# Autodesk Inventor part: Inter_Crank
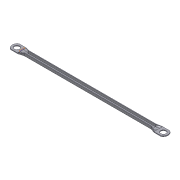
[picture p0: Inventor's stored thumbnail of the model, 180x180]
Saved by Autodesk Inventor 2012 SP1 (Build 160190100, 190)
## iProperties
Created: 2006-03
Part Number: Inter_Crank
Document SubType Name: Modeling
Material: Stainless Steel, 440C
Density: 7.75 g/cm^3
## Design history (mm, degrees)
sketch "Sketch1"
  geometry: L1 (0, 0)-(0, 1.6); L2 (0, 1.6)-(4.6, 1.6); L3 (4.6, 1.6)-(4.6, 8); L4 (4.6, 8)-(6.2, 8); L5 (6.2, 8)-(6.2, 1.5); L6 (4.7, 0)-(0, 0); L7 (0, 10.493)-(0, -1.142) reference; L8 (-4.6, 1.6)-(-4.6, 8); L9 (-4.6, 8)-(-6.2, 8); L10 (-6.2, 8)-(-6.2, 1.5); L11 (0, 1.6)-(-4.6, 1.6); L12 (-4.7, 0)-(0, 0); A1 r 1.5 centre (4.7, 1.5) between (4.7, 0) and (6.2, 1.5); A2 r 1.5 centre (-4.7, 1.5) between (-6.2, 1.5) and (-4.7, 0)
  constraints: 22 end point, 6 symmetric about line, 4 parallel, 4 point on circle, 2 centre point, 2 perpendicular, 2 tangent, 1 vertical, 1 other
  dimensions: "d1" = 4.6 distance between parallel lines of L3 L1; "d2" = 8 distance between parallel lines of L6 L4; "d3" = 1.6 distance between parallel lines of L5 L3; "d4" = 1.5 radius of A1
extrude "Extrusion1" new body sketch "Sketch1" distance "d5" = 175; taper "d6" = 0 deg
workplane "Work Plane1"
sketch "Sketch2"
  geometry: L1 (-0.8, 0)-(10.4, 0) reference; L2 (3, 12)-(5, 12); L3 (5, 12)-(5, -12); L4 (5, -12)-(3, -12); L5 (3, -12)-(3, 12); L6 (3, 12)-(5, -12); L7 (1.5, 6.2)-(8, 6.2) reference; L8 (8, -6.2)-(1.5, -6.2) reference; L9 (0, -4.7)-(0, 4.7) reference; 2 further points
  constraints: 10 end point, 2 parallel, 1 horizontal, 1 midpoint, 1 perpendicular, 1 point on line
  dimensions: "d8" = 4 distance from line of point (4, 0) L9; "d9" = 2 distance of L2.start L2.end; "d10" = 24 distance of L2.end L3.end
loft "Loft1" sketch "Sketch2" dims "d11" = 0, "d12" = 90 deg, "d13" = 0, "d14" = 90 deg
  node "Edges1"
sketch "Sketch3"
  geometry: L1 (2, 12.374)-(2, 18.469) reference; L2 (2, 19.993)-(0, 19.993) reference; L3 (2, 18.469)-(2, 19.993) reference; L4 (2, 3.612)-(2, 12.374) reference; L5 (2, -2.483)-(2, 3.612) reference; L6 (2, -4.007)-(2, -2.483) reference; L7 (0, -4.007)-(2, -4.007) reference; L8 (0, 0)-(0, -4.007) reference; L9 (0, 15.986)-(0, 0) reference; L10 (0, 19.993)-(0, 15.986) reference; 1 further point
extrude "Extrusion2" join sketch "Sketch3" distance "d15" = 20; taper "d16" = 0 deg
sketch "Sketch4"
  geometry: L1 (-20.8, 12)-(270.4, 12) reference; L2 (0, 24)-(0, 0); A1 r 14 centre (7.211, 12) between (0, 24) and (0, 0); 1 further point
  constraints: 3 point on circle, 2 end point, 1 centre point, 1 perpendicular, 1 point on line
  dimensions: "d17" = 14 radius of A1
extrude "Extrusion3" join sketch "Sketch4" stored distance "d18" = 20; taper "d19" = 0 deg
sketch "Sketch5"
  geometry: L1 (-48.268, 4.381)-(252.437, 4.381) reference; L2 (0, 12.374)-(0, -3.612) reference; C1 r 7.5 at (-14, 4.381); 1 further point
  constraints: 1 centre point, 1 point on line
  dimensions: "d20" = 15 diameter of C1; "d21" = 14 distance from line of C1.centre L2
extrude "Extrusion4" cut sketch "Sketch5" stored distance "d22" = 20; taper "d23" = 0 deg
mirror "Mirror1"
body "Solid1"
other parameters: "d7" = 13
